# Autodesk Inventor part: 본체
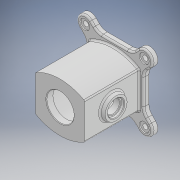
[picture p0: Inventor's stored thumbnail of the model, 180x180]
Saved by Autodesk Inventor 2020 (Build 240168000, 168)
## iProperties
Created: 2022-01
Part Number: 본체
Material: 일반
Document SubType Name: Modeling
Designer: user
Density: 1 g/cm^3
Appearance: 기본값
Author: user
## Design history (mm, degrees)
sketch "스케치1"
  geometry: L1 (53, -53)-(31.787, -53); L2 (-53, -53)-(-53, -31.787); L3 (-53, 53)-(-31.787, 53); L4 (53, 53)-(53, 31.787); L5 (53, -53)-(-53, 53); L6 (-53, -53)-(53, 53); L7 (0, 0)-(54.447, 54.447); L8 (53, 31.787)-(65.054, 43.841); L9 (65.054, 43.841)-(43.841, 65.054); L10 (43.841, 65.054)-(31.787, 53); L11 (0, 77)-(0, 0); L12 (-53, 0)-(53, 0); L13 (65.054, -43.841)-(43.841, -65.054); L14 (43.841, -65.054)-(31.787, -53); L15 (53, -31.787)-(65.054, -43.841); L16 (-53, 31.787)-(-65.054, 43.841); L17 (-43.841, 65.054)-(-31.787, 53); L18 (-65.054, 43.841)-(-43.841, 65.054); L19 (-53, -31.787)-(-65.054, -43.841); L20 (-53, 53)-(-53, -53); L21 (-43.841, -65.054)-(-31.787, -53); L22 (-65.054, -43.841)-(-43.841, -65.054); L23 (-31.787, 53)-(31.787, 53); L24 (-53, 31.787)-(-53, 53); L25 (-53, -31.787)-(-53, 31.787); L26 (-31.787, -53)-(-53, -53); L27 (31.787, -53)-(-31.787, -53); L28 (53, -31.787)-(53, -53); L29 (53, 31.787)-(53, -31.787); L30 (31.787, 53)-(53, 53); A1 r 77 centre (0, 0) between (54.447, 54.447) and (0, 77); A2 r 15 centre (54.447, 54.447) between (65.054, 43.841) and (43.841, 65.054); A3 r 15 centre (54.447, -54.447) between (43.841, -65.054) and (65.054, -43.841); A4 r 15 centre (-54.447, 54.447) between (-43.841, 65.054) and (-65.054, 43.841); A5 r 15 centre (-54.447, -54.447) between (-65.054, -43.841) and (-43.841, -65.054); 4 further points
  constraints: 60 end point, 20 parallel, 18 symmetric about line, 10 perpendicular, 10 point on circle, 5 centre point, 5 coincident, 3 horizontal, 3 midpoint, 3 point on line, 1 tangent, 1 vertical, 3 other
  dimensions: "d0" = 106 distance of L3.start L4.start; "d1" = 106 distance of L2.start L3.start; "d2" = 154 diameter of A1; "d3" = 30 distance of L9.end L8.end
extrude "돌출1" new body sketch "스케치1" distance "d5" = 10; taper "d6" = 0 deg
fillet "모깎기1" dims "d7" = 20
sketch "스케치2"
  geometry: L1 (-45, -45)-(45, -45); L2 (45, -45)-(45, -32.942); L3 (45, 45)-(-45, 45); L4 (-45, 45)-(-45, 32.942); L5 (-45, -45)-(45, 45); L6 (45, -45)-(-45, 45); L7 (23.503, 53)-(-23.503, 53) reference; L8 (0, 53)-(0, -102.759); L9 (-23.503, -53)-(23.503, -53) reference; L10 (0, -53)-(0, 133.389); L11 (45, 32.942)-(45, 45); L12 (45, -32.942)-(45, 32.942); L13 (-45, -32.942)-(-45, -45); L14 (-45, 32.942)-(-45, -32.942); A1 r 90 centre (0, -45) between (45, 32.942) and (-45, 32.942); A2 r 90 centre (0, 45) between (-45, -32.942) and (45, -32.942); 1 further point
  constraints: 24 end point, 10 parallel, 6 point on circle, 5 midpoint, 4 point on line, 3 perpendicular, 2 centre point, 1 horizontal, 1 vertical
  dimensions: "d8" = 90 distance of L3.end L3.start; "d9" = 90 distance of L3.start L1.end; "d10" = 180 diameter of A1
extrude "돌출2" join sketch "스케치2" distance "d11" = 100; taper "d12" = 0 deg
sketch "스케치3"
  geometry: L1 (10, 32.942)-(-100, 32.942); L2 (-100, 65.885)-(-100, 0) reference; L3 (10, 9.44)-(10, 56.445) reference; C1 r 20 at (-50, 32.942)
  constraints: 2 end point, 1 centre point, 1 midpoint, 1 point on line
  dimensions: "d13" = 40 diameter of C1; "d14" = 60 distance from line of L3 C1.centre
extrude "돌출3" join sketch "스케치3" distance "d15" = 8; taper "d16" = 0 deg
feature "면 기울기1" dims angle "d17" = 15 deg
sketch "스케치4"
  geometry: A1 r 15 centre (-54.447, 54.447) between (-43.841, 65.054) and (-65.054, 43.841) reference; A2 r 15 centre (54.447, 54.447) between (65.054, 43.841) and (43.841, 65.054) reference; A3 r 15 centre (54.447, -54.447) between (43.841, -65.054) and (65.054, -43.841) reference; A4 r 15 centre (-54.447, -54.447) between (-65.054, -43.841) and (-43.841, -65.054) reference; 5 further points
  constraints: 4 coincident
hole "구멍1" sketch "스케치4" at (-54.447, 54.447), (54.447, 54.447), (54.447, -54.447), (-54.447, -54.447) diameter "d18" = 9; stored, may be unused: countersink angle "d22" = 90 deg, drill point angle "d24" = 0 deg; dims "d19" = 8, "d20" = 18, "d21" = 2, "d23" = 10
sketch "스케치5"
  geometry: L1 (-54.447, 54.447)-(54.447, -54.447); L2 (54.447, -54.447)-(-54.447, -54.447); L3 (-54.447, -54.447)-(54.447, 54.447); C1 r 4.5 at (-54.447, 54.447) reference; C2 r 4.5 at (54.447, -54.447) reference; C3 r 4.5 at (-54.447, -54.447) reference; A1 r 40 centre (0, 0) between (-28.284, 28.284) and (-28.284, -28.284); A2 r 15 centre (54.447, 54.447) between (65.054, 43.841) and (43.841, 65.054) reference; 3 further points
  constraints: 6 end point, 4 point on circle, 4 point on line, 1 centre point, 1 coincident, 1 horizontal, 1 perpendicular
  dimensions: "d25" = 80 diameter of A1
hole "구멍2" sketch "스케치5" at (-28.284, 28.284), (-28.284, -28.284), (28.284, -28.284), (28.284, 28.284) diameter "d26" = 3.242; stored, may be unused: countersink angle "d30" = 90 deg, drill point angle "d32" = 118 deg; dims "d27" = 8, "d28" = 18, "d29" = 2, "d31" = 10
sketch "스케치6"
  geometry: C1 r 25 at (0, 0); 1 further point
  constraints: 1 centre point, 1 coincident
  dimensions: "d33" = 50 diameter of C1
extrude "돌출4" cut sketch "스케치6" distance "d34" = 12; taper "d35" = 0 deg
sketch "스케치7"
  geometry: C1 r 37 at (0, 0); 1 further point
  constraints: 1 centre point, 1 coincident
  dimensions: "d36" = 74 diameter of C1
extrude "돌출5" cut sketch "스케치7" distance "d37" = 86; taper "d38" = 0 deg
sketch "스케치8"
  geometry: C1 r 25 at (0, 0); 1 further point
  constraints: 1 centre point, 1 coincident
  dimensions: "d39" = 50 diameter of C1
extrude "돌출6" cut sketch "스케치8" distance "d40" = 12; taper "d41" = 0 deg
sketch "스케치9"
  geometry: C1 r 20 at (0, 0) reference; 2 further points
  constraints: 1 coincident
hole "구멍3" sketch "스케치9" at (0, 0) diameter "d42" = 24; stored, may be unused: countersink angle "d46" = 90 deg, drill point angle "d48" = 0 deg; dims "d43" = 8, "d44" = 30, "d45" = 5, "d47" = 10
chamfer "모따기1" distance "d49" = 1; stored, may be unused: second distance "d50" = 2, angle "d51" = 45 deg
fillet "모깎기2" dims "d52" = 3
fillet "모깎기3" dims "d53" = 3
fillet "모깎기4" dims "d54" = 3
fillet "모깎기5" dims "d55" = 3
chamfer "모따기2" distance "d56" = 1; stored, may be unused: second distance "d57" = 2, angle "d58" = 45 deg
fillet "모깎기6" dims "d59" = 3
node "작업 평면1"
sketch "스케치10"
  geometry: L1 (-26, 0)-(26, 0) reference; L2 (53, 44)-(53, 76) reference; 2 further points
  constraints: 1 other
  dimensions: "d61" = 60 distance from line of L1 point (0, 60); "d62" = 53 distance from line of point (0, 60) L2
feature "엠보싱1" sketch "스케치10" dims "d63" = 0.5, "d64" = 0
node "솔리드1"
feature "A9D066F2-1C7D-4E18-AEED-F7BC21143FA4" dims "d18" = 9, "d19" = 8, "d20" = 18, "d21" = 2, "d22" = 90 deg, "d23" = 10, "d24" = 0
other parameters: "d60" = 0
